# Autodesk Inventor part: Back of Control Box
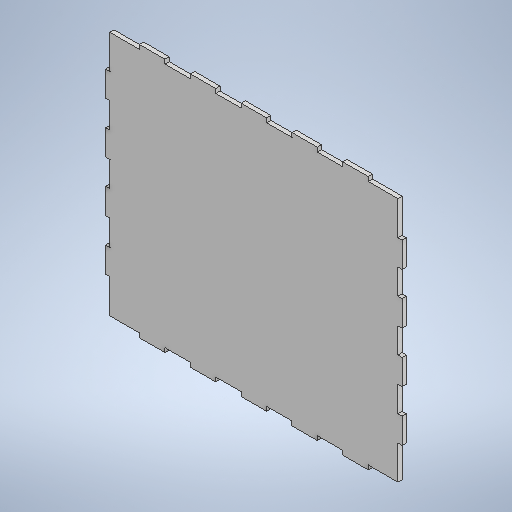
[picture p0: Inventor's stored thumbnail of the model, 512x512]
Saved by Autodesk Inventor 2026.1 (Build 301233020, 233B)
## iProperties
Created: 2026-11
Part Number: Back of Control Box
Material: Generic
Document SubType Name: Modeling
Designer: hp
Density: 1 g/cm^3
Appearance: Default
Author: hp
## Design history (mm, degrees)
sketch "Sketch1"
  geometry: L1 (0, 300)-(350, 300); L2 (350, 300)-(350, 0); L3 (350, 0)-(0, 0); L4 (0, 0)-(0, 300); L5 (190, 0)-(160, 0); L6 (160, 0)-(160, 5); L7 (160, 5)-(190, 5); L8 (190, 5)-(190, 0); L9 (130, 0)-(100, 0); L10 (100, 0)-(100, 5); L11 (100, 5)-(130, 5); L12 (130, 5)-(130, 0); L13 (70, 0)-(40, 0); L14 (40, 0)-(40, 5); L15 (40, 5)-(70, 5); L16 (70, 5)-(70, 0); L17 (250, 0)-(220, 0); L18 (220, 0)-(220, 5); L19 (220, 5)-(250, 5); L20 (250, 5)-(250, 0); L21 (190, 0)-(160, 0); L22 (160, 0)-(160, 5); L23 (160, 5)-(190, 5); L24 (190, 5)-(190, 0); L25 (130, 0)-(100, 0); L26 (100, 0)-(100, 5); L27 (100, 5)-(130, 5); L28 (130, 5)-(130, 0); L29 (310, 0)-(280, 0); L30 (280, 0)-(280, 5); L31 (280, 5)-(310, 5); L32 (310, 5)-(310, 0); L33 (250, 0)-(220, 0); L34 (220, 0)-(220, 5); L35 (220, 5)-(250, 5); L36 (250, 5)-(250, 0); L37 (190, 0)-(160, 0); L38 (160, 0)-(160, 5); L39 (160, 5)-(190, 5); L40 (190, 5)-(190, 0); L41 (350, 150)-(0, 150); L42 (175, 300)-(175, 0); L43 (250, 295)-(250, 300); L44 (250, 300)-(220, 300); L45 (220, 300)-(220, 295); L46 (220, 295)-(250, 295); L47 (190, 295)-(190, 300); L48 (190, 300)-(160, 300); L49 (160, 300)-(160, 295); L50 (160, 295)-(190, 295); L51 (70, 295)-(70, 300); L52 (100, 300)-(100, 295); L53 (100, 295)-(130, 295); L54 (130, 300)-(100, 300); L55 (130, 295)-(130, 300); L56 (70, 300)-(40, 300); L57 (40, 300)-(40, 295); L58 (40, 295)-(70, 295); L59 (280, 295)-(310, 295); L60 (310, 295)-(310, 300); L61 (310, 300)-(280, 300); L62 (280, 300)-(280, 295); L63 (190, 295)-(190, 300); L64 (250, 300)-(220, 300)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; 153 further points
  constraints: 308 end point, 90 symmetric about line, 8 parallel, 6 midpoint, 5 horizontal, 4 perpendicular, 2 vertical, 1 coincident, 1 point on line, 147 other
  dimensions: "d8" = 350 distance of L2.end L3.end; "d9" = 300 distance of L1.end L2.end; "d10" = 30 distance of L6.end L7.end; "d11" = 5 distance of L5.end L6.end; "d12" = 60 distance of L5.start L9.start; "d13" = 60 distance of L5.start L17.start; "d14" = 5 distance of L81.end L80.end; "d15" = 30 distance of L80.end L79.end; "d16" = 60 distance of L79.end L83.end; "d17" = 60 distance of L79.end L91.end; "d18" = 5 distance between parallel lines of L1 L151
extrude "Extrusion1" new body sketch "Sketch1" distance "d19" = 5; taper "d20" = 0 deg
body "Solid1"
node "Sketch Rectangular Pattern2" dims "d12" = 60, "d13" = 60
node "Sketch Rectangular Pattern4" dims "d16" = 60, "d17" = 60
